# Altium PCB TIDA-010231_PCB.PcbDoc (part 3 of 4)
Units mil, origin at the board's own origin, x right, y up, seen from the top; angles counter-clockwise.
Board outline 3937.01 x 3740.16 mil, 4 copper layers (Top Layer, Signal Layer 1, Signal Layer 2, Bottom Layer), stack 65.355 mil thick; 295 components, 163 nets, 818 pads, 213 vias.
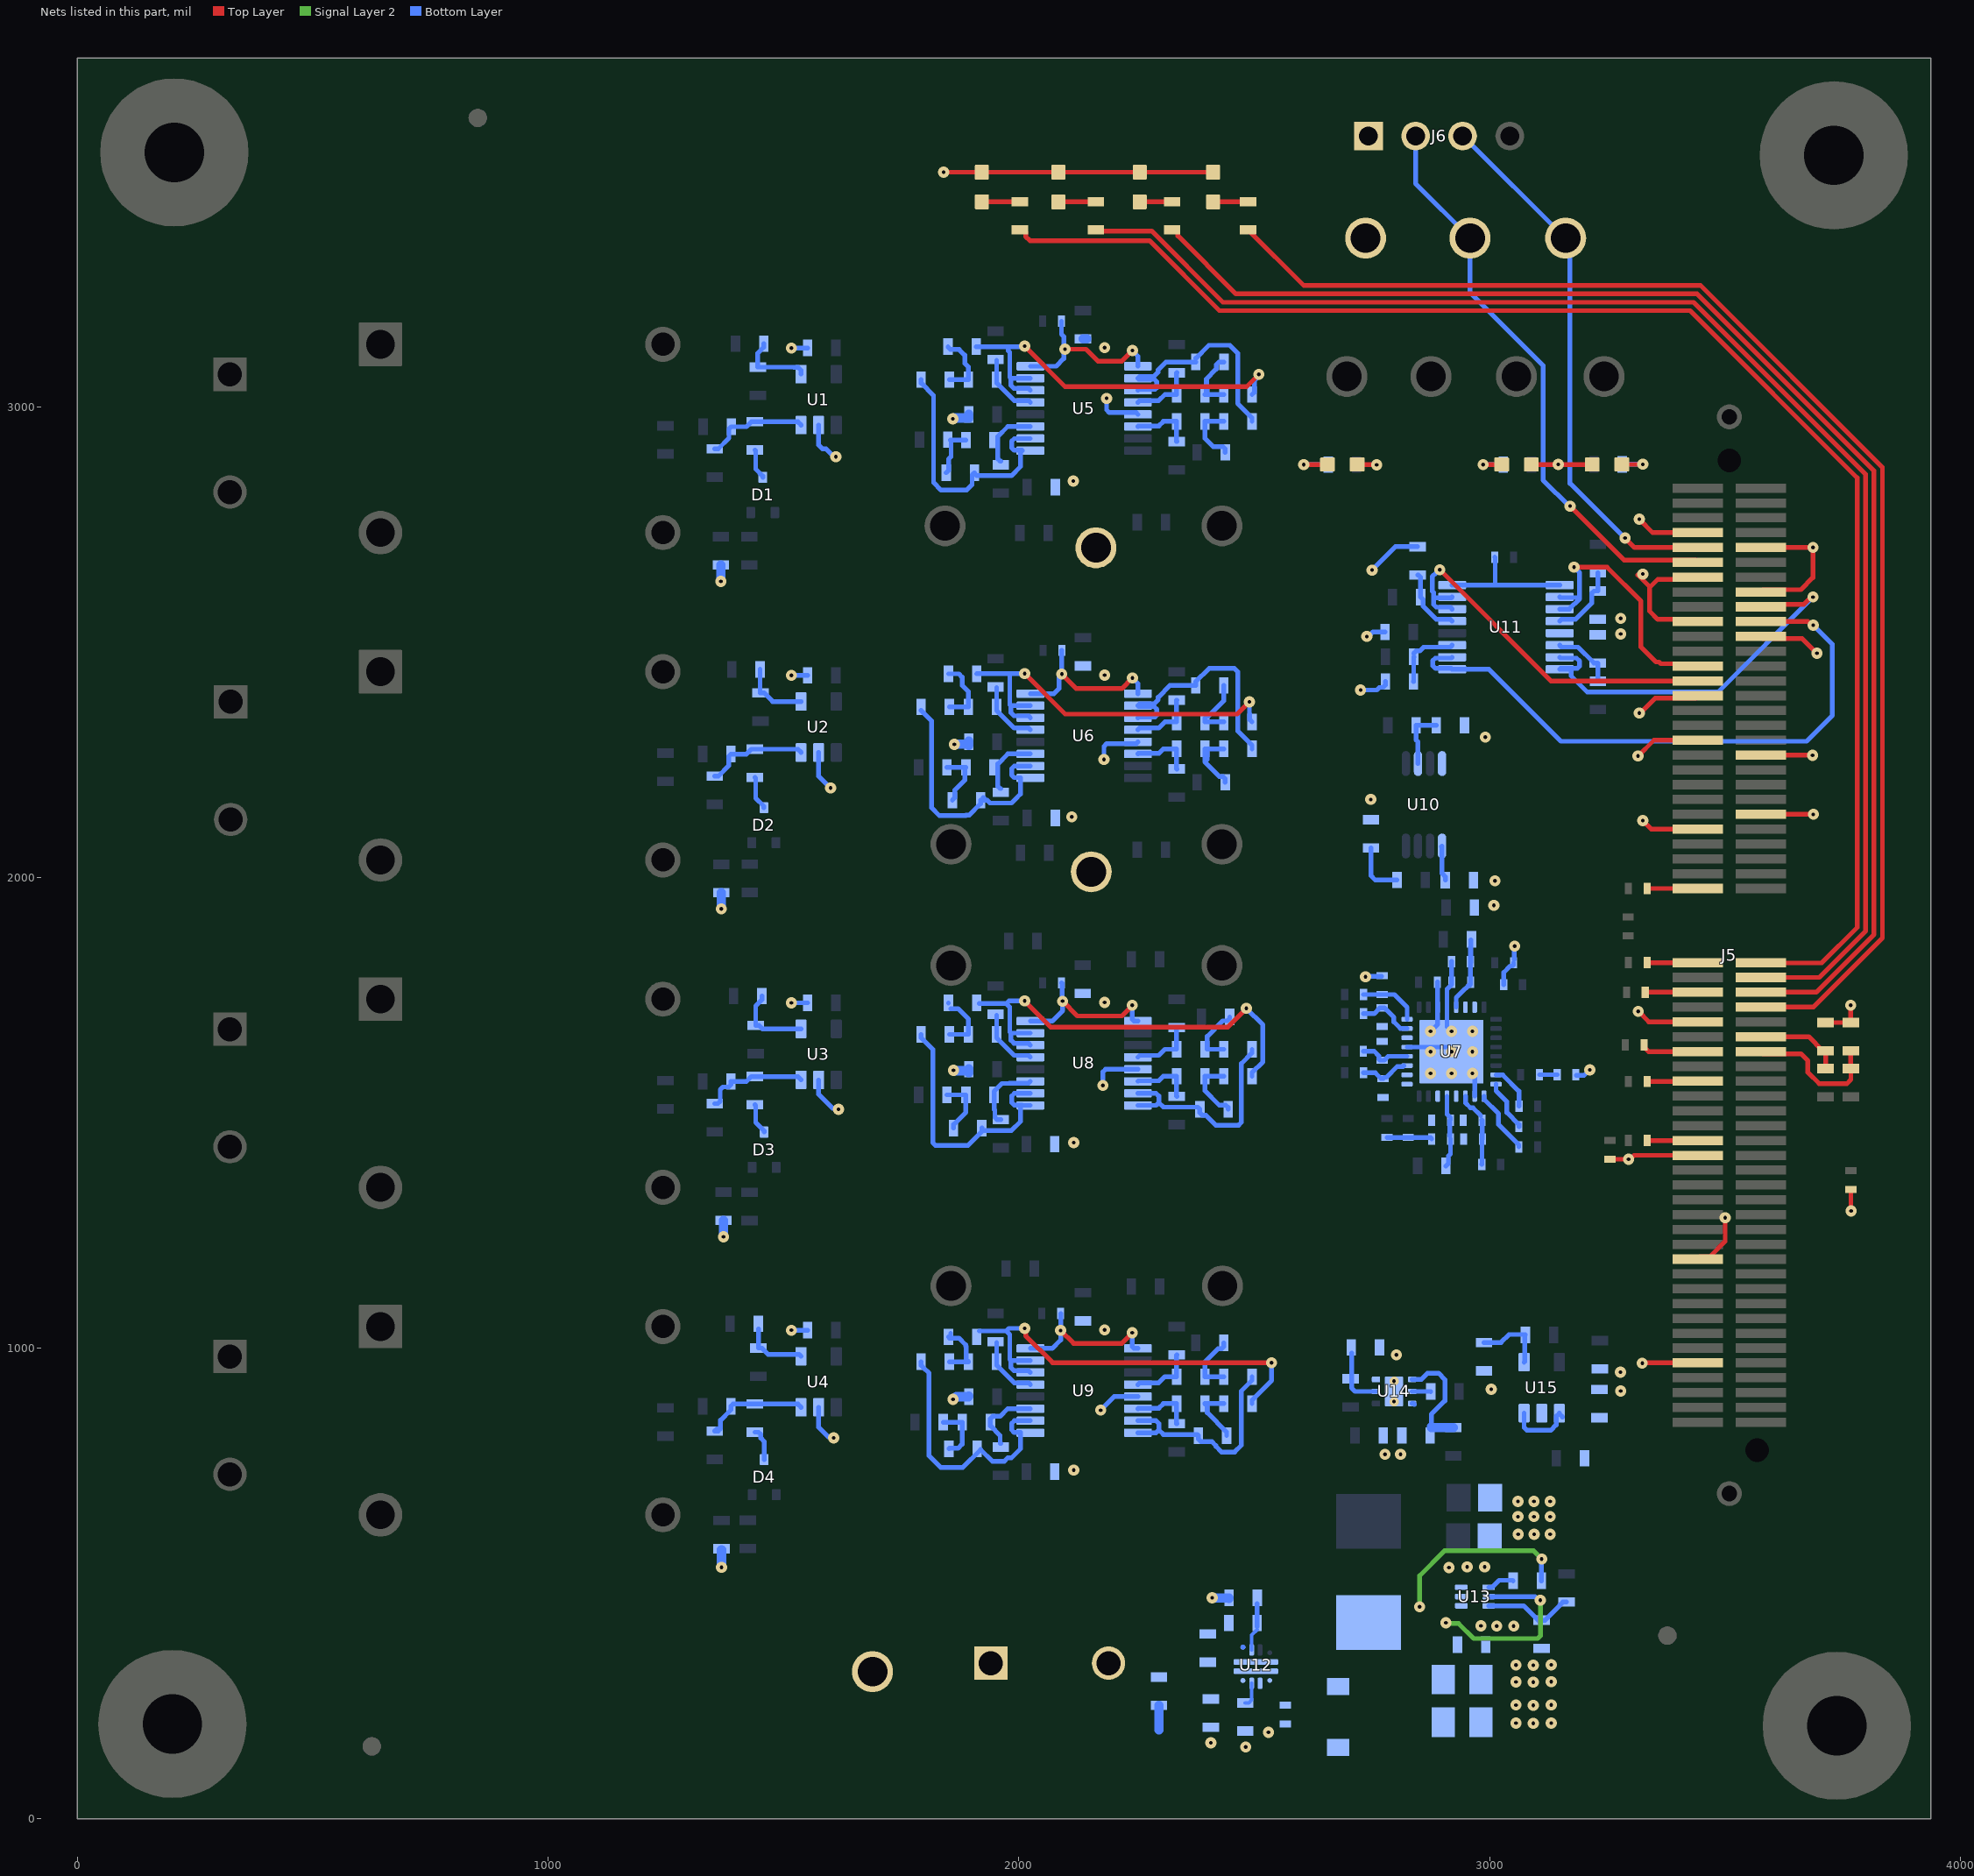
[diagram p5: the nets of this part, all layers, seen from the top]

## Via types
v1: diameter 23.62, hole 7.87, Top Layer to Bottom Layer, 211 vias
v2: diameter 19.68, hole 7.87, Top Layer to Bottom Layer, 2 vias

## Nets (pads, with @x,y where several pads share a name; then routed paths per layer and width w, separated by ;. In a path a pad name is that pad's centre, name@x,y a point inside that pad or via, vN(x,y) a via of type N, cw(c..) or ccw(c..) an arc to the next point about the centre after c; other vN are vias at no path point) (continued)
GND: C2.2 C4.2 C6.2 C8.2 C9.2 C10.2 C19.2 C20.2 C21.2 C22.2 C23.2 C24.2 C31.2 C32.2 C35.1 C36.2 C37.2 C38.2 C39.2 C46.2 C49.2 C50.2 C51.2 C52.2 C53.1 C60.2 C63.2 C64.2 C65.2 C66.2 C67.2 C68.2 C69.2 C70.2 C71.2 C72.2 C74.2 C75.2 C76.2 C77.2 C79.2 C80.1 C81.2 C83.2 C84.2 C85.2 C86.2 C87.2 C88.2 C89.2 C90.2 D5.1 D6.1 D7.1 D8.1 D9.2 D10.1 D11.1 D12.1 J5.7 J5.10 J5.13 J5.16 J5.19 J5.22 J5.29 J5.35 J5.38 J5.46 J5.47 J5.65 J5.83 J5.97 J5.111 J6.1 J7.1 R42.2 R51.1 R52.1 R81.1 R82.1 R90.1 R91.1 R99.1 R102.1 R103.1 R112.1 R113.1 R114.1 R115.1 R119.1 TP12.1 TP13.1 TP14.1 TP15.1 U1.2 U2.2 U3.2 U4.2 U5.13 U6.13 U7.1 U7.2 U7.5 U7.6 U7.11 U7.12 U7.14 U7.15 U7.26 U7.28 U7.30 U7.33 U8.13 U9.13 U10.4 U11.13 U12.8 U13.3 U14.3 U14.7@2797.02,908.01 U15.2 | length 5129.4
  Top Layer w10: v1@1837.47,3495.42 v1(1840.09,3498.03) D5.1@1921.29,3498.03 D6.1@2083.96,3498.03 D7.1@2256.73,3498.03 D8.1@2412.57,3498.03 ; D10.1@2718.55,2877.17 2718.97,2876.75 2759.52,2876.75 v1(2759.94,2876.33) ; v1@2799.83,983.8 v1(2801.83,985.8) ; D12.1@3088.56,2877.17 v1(3145.99,2877.17) D11.1@3217.94,2877.17 ; R42.2@3256.02,1401.22 v1(3295.1,1401.22) 3298.78,1401.22 3307.1,1409.54 J5.83@3442.42,1409.54 ; v1@3315.1,2257.32 3349.2,2291.42 J5.35@3442.42,2291.42 ; v1@3315.1,2642.51 3339.87,2617.74 3339.87,2615.5 ; v1(3315.91,1715.55) 3315.91,1715.44 3338.35,1693 J5.65@3442.42,1693 ; v1(3317.96,2760.83) 3346.42,2732.37 J5.7@3442.42,2732.37 ; v1@3318.6,2347.54 3352.12,2381.07 3437.58,2381.07 J5.29@3442.42,2385.91 ; v1@3324.41,967.91 3325.1,968.59 J5.111@3442.42,968.59 ; v1(3325.64,2120.57) 3343.76,2102.45 J5.47@3442.42,2102.45 ; J5.97@3442.42,1189.06 3447.27,1193.9 3467.44,1193.9 3500.37,1226.84 v1(3500.37,1277.04) ; J5.19@3442.42,2543.39 3437.58,2548.24 3357.41,2548.24 3339.87,2565.78 3339.87,2615.5 ; J5.13@3442.42,2637.88 3437.58,2633.04 3357.41,2633.04 3339.87,2615.5 ; J5.46@3576.28,2133.94 v1(3687.75,2133.94) ; J5.38@3576.28,2259.93 v1@3686.97,2259.93 ; J5.22@3576.28,2511.9 3581.13,2507.06 3664.27,2507.06 v1(3695.24,2476.08) v1@3695.24,2475.99 ; J5.16@3576.28,2606.39 3581.13,2611.23 3661.3,2611.23 3686.97,2636.9 v1(3686.97,2700.87) J5.10@3576.28,2700.87 ; R103.1@3715.31,1691.5 3715.44,1691.63 3766.95,1691.63 3767.07,1691.75 3767.07,1728.22 v1(3767.21,1728.36) ; R99.1@3767.21,1337.13 3767.63,1336.7 3767.63,1291.65 v1(3768.05,1291.23)
  Bottom Layer w10: v1(1516.53,1038.05) C90.2@1550.98,1038.05 ; v1(1516.53,1733.58) C89.2@1550.98,1733.62 ; v1(1516.53,2429.11) C88.2@1550.98,2429.13 ; v1(1516.53,3124.64) C87.2@1550.98,3124.64 ; U4.2@1574.6,874.29 1574.69,874.2 1574.69,831.76 1594.51,811.94 1603.94,811.94 v1(1606.55,809.33) ; U3.2@1574.6,1569.8 1574.6,1539.06 1603.84,1509.81 1613.92,1509.81 v1(1616.52,1507.2) ; U2.2@1574.6,2265.31 1574.69,2265.2 1574.69,2214.95 v1(1599.83,2189.81) ; U1.2@1574.6,2960.83 1574.69,2960.74 1574.69,2918.35 1582.79,2910.25 1590.55,2910.25 1607.3,2893.5 v1(1610.98,2893.5) ; v1(2173.66,868.11) 2202.48,896.93 U9.13@2252.8,896.93 ; v1(2178.35,1558.11) 2178.35,1586.58 2184.2,1592.44 U8.13@2252.8,1592.44 ; v1(2180.64,2250.68) 2180.64,2278.24 2186.5,2284.09 2248.94,2284.09 U6.13@2252.8,2287.95 ; v1(2186.18,3017.64) 2186.18,2993.18 2192.04,2987.32 2248.94,2987.32 U5.13@2252.8,2983.46 ; v1(2725.85,2397.99) 2760.33,2397.99 2765.96,2403.61 2773.46,2403.61 2778.46,2408.61 R90.1@2778.46,2416.11 ; v1(2736.33,1788.99) 2737.47,1790.13 C36.2@2770.51,1790.13 ; v1(2739.19,2511.77) 2742.87,2511.77 2752.56,2521.46 C71.2@2777.97,2521.46 ; v1(2750.34,2652.82) 2800.02,2702.51 R82.1@2847.01,2702.51 ; C60.2@2782.14,1447.52 C46.2@2827.02,1447.52 2874.39,1447.52 2876.89,1445.02 C22.2@2876.89,1444.39 ; U7.5@2824.69,1639.56 2909.33,1639.56 v1(2919.18,1629.72) ; v1(2874.62,1672.91) 2889.65,1687.94 U7.11@2889.65,1724.2 2889.57,1724.28 2889.57,1777.51 C53.1@2889.33,1777.75 ; v1(2919.18,1672.91) 2909.33,1682.75 U7.12@2909.33,1724.2 2909.33,1762.51 2919.5,1772.68 2919.37,1772.8 2919.37,1821.09 C32.2@2919.25,1821.22 ; v1(2963.66,1583.6) 2968.39,1578.87 U7.26@2968.39,1535.23 ; R52.1@3030,1772.19 3030,1797.9 3043.82,1811.72 3048.32,1811.72 3050.82,1814.22 R51.1@3050.82,1818.72 ; R51.1@3052.13,1825.72 3052.13,1852.61 v1(3053.44,1853.92) ; C35.1@3184.74,1579.5 3200.79,1579.5 3212.21,1590.93 v1(3212.94,1590.93)
  Bottom Layer w20: v1@1366.79,2629.07 C2.2@1366.79,2663.69 ; C4.2@1367.61,1967.76 1367.75,1967.76 1367.75,1933.12 v1(1367.89,1932.98) ; v1(1368.29,534.1) C8.2@1368.29,571.56 ; C6.2@1372.28,1271.38 1372.41,1271.38 1372.41,1236.72 v1(1372.55,1236.58) ; v1(1859.76,2974.06) 1860.74,2974.06 1862.73,2976.04 1893.66,2976.04 C67.2@1893.66,2983.54 ; v1(1860.24,891.11) 1861.22,891.11 1867.11,897.01 1892.69,897.01 C70.2@1893.66,897.98 ; v1(1861.2,1590.09) 1861.89,1589.4 1889.28,1589.4 1893.66,1585.02 C69.2@1893.66,1592.52 C69.2@1893.66,1593.49 ; v1(1862.75,2282.6) 1863.45,2283.29 C68.2@1893.66,2283.29 ; C68.2@1893.66,2280.53 C68.2@1893.66,2283.29 ; C68.2@1893.66,2288.52 C68.2@1893.66,2288.03 ; C68.2@1893.66,2289 C68.2@1893.66,2288.03 ; C10.2@2136.3,3143.91 C10.2@2143.8,3143.91 ; v1(2173.66,868.11) v1@2174.44,868.11 ; 2297.65,189.04 C72.2@2297.65,241.3 ; v1(2410.44,469.56) 2410.79,469.21 2446.39,469.21 R112.1@2446.39,468.86 ; C68.2@1893.66,2283.29 C68.2@1893.66,2288.03
  other v1: 2481.8,152.79 2407.9,161.48 2530.2,183.97 3056.13,203.27 3092.88,202.82 3131.03,203.54 3092.88,241.3 3056.13,241.75 3131.03,242.02 3092.88,290.48 3056.13,290.93 3131.03,291.2 3092.88,326.36 3056.13,326.81 3131.03,327.08 3015.22,409.49 3051.14,409.49 2981.76,409.96 2913.82,533.84 2952.11,535.4 2989.57,535.4 3060.72,604.52 3094.58,604.52 3128.44,604.52 3060.09,641.95 3094.26,641.95 3128.44,641.95 3060.35,674.26 3094.39,674.26 3128.44,674.26 2116.55,741.04 2777.9,774.45 2810.8,774.45 3278.59,908.86 3003.44,912.78 3277.91,948.82 3324.33,967.91 2182.26,1038.76 2116.56,1436.55 2874.62,1583.6 2919.18,1583.6 2874.62,1629.72 2963.66,1629.72 2963.66,1672.91 2182.26,1734.28 3009.16,1940.45 3011.57,1992.9 2112.29,2128.69 2747.48,2165.54 3315.13,2258.06 3686.09,2259.47 2990.96,2297.82 3317.96,2349.03 2182.26,2429.79 3278.59,2517.32 3278.59,2550.06 1366.93,2628.93 3325.64,2644.47 2115.4,2841.81 2182.26,3125.3
  other v2: 2797.02,886.36 2797.02,929.67
GPIO4: J5.68 R101.2 R103.2 | length 189.7
  Top Layer w10: J5.68@3576.28,1661.5 3677.81,1661.5 3707.81,1631.5 3715.31,1631.5 3713.78,1629.98 R101.2@3713.78,1593.91
GPIO5: J5.70 R100.1 R102.2 | length 299
  Top Layer w10: J5.70@3576.28,1630.01 3581.13,1625.17 3661.3,1625.17 3676.12,1610.34 3676.12,1585.86 3700.18,1561.8 3758.81,1561.8 3767.67,1570.66 R100.1@3767.67,1593.91 3767.07,1594.51 R102.2@3767.07,1631.75
IntADC1In: J5.25 U11.10 U11.11 | length 574.1
  Top Layer w10: v1(3179.25,2659.1) 3249.43,2659.1 3321.61,2586.93 3321.61,2489.55 3353.47,2457.69 3359.87,2457.69 3363.8,2453.75 3437.58,2453.75 J5.25@3442.42,2448.91
  Bottom Layer w10: U11.11@3148.79,2569.97 3169.46,2569.97 3191.19,2591.7 3191.19,2593.99 ; U11.10@3148.79,2595.56 3150.04,2594.3 3190.87,2594.3 3191.19,2593.99 ; v1(3179.25,2659.1) 3191.19,2647.16 3191.19,2593.99
IntADC2In: J5.27 U11.6 U11.7 | length 813.7
  Top Layer w10: v1(2894.14,2653.48) 3130.21,2417.41 J5.27@3442.42,2417.41
  Bottom Layer w10: v1(2894.14,2653.48) 2888.23,2647.56 2886.9,2647.56 2878.04,2638.7 2878.04,2608.1 2881.05,2605.09 2881.05,2589.84 ; U11.6@2920.44,2569.97 2916.58,2573.83 2886.9,2573.83 2881.05,2579.68 2881.05,2589.84 ; U11.7@2920.44,2595.56 2918.71,2593.83 2885.03,2593.83 2881.05,2589.84
IntADC3In: J5.20 U11.1 U11.2 | length 1316.5
  Top Layer w10: J5.20@3576.28,2543.39 3676.34,2543.39 3683.87,2535.87 v1(3687.56,2535.87)
  Bottom Layer w10: U11.2@2920.44,2467.61 2918.71,2465.87 2884.86,2465.87 2879,2460.02 2879,2450 2885.25,2443.75 2918.71,2443.75 U11.1@2920.44,2442.02 2998.53,2442.02 3151.46,2289.08 3673.39,2289.08 3728.35,2344.03 3728.35,2495.08 v1(3687.56,2535.87)
IntADC4In: J5.18 U11.15 U11.16 | length 868.5
  Top Layer w10: J5.18@3576.28,2574.89 3581.13,2579.73 3667.46,2579.73 3683.28,2595.56 v1(3686.97,2595.56)
  Bottom Layer w10: U11.15@3148.79,2467.61 3150.52,2465.87 3184.52,2465.87 3191.19,2459.2 3191.19,2448.8 3186.13,2443.75 3150.52,2443.75 U11.16@3148.79,2442.02 3169.46,2442.02 3173.32,2438.16 3173.32,2427.88 3207.39,2393.81 3485.22,2393.81 v1(3686.97,2595.56)
NetC1_1: C1.1 R3.2 R4.2 U1.3 | length 221.7
  Bottom Layer w10: C1.1@1353.67,2910.42 1361.17,2910.42 1384.08,2933.33 1384.08,2952.48 R4.2@1389.08,2957.48 1421.11,2957.48 1431.58,2967.95 1530.39,2967.95 1537.2,2961.14 U1.3@1537.2,2960.83
NetC3_1: C3.1 R8.2 R9.2 U2.3 | length 222.2
  Bottom Layer w10: C3.1@1353.67,2214.91 1361.17,2214.91 1383.23,2236.97 1383.23,2256.94 R9.2@1388.23,2261.94 1421.11,2261.94 1431.58,2272.42 1530.39,2272.42 1537.2,2265.6 U2.3@1537.2,2265.31
NetC5_1: C5.1 R13.2 R14.2 U3.3 | length 228.7
  Bottom Layer w10: C5.1@1353.67,1519.4 1360.32,1519.36 1365.36,1524.4 1365.36,1548.85 1371.22,1554.71 1383.23,1554.71 1388.23,1559.71 R14.2@1388.23,1566.41 1421.11,1566.41 1431.58,1576.88 R13.2@1439.08,1576.92 1530.39,1576.88 1537.2,1570.07 U3.3@1537.2,1569.8
NetC7_1: C7.1 R18.2 R19.2 U4.3 | length 231.9
  Bottom Layer w10: C7.1@1358.23,828.38 1353.67,823.83 1361.11,823.83 1366.17,828.89 1366.17,846.9 1388.23,868.95 R19.2@1388.23,876.45 1393.19,881.41 1439.02,881.41 R18.2@1439.08,881.41 1530.39,881.35 1537.2,874.54 U4.3@1537.2,874.23
NetC11_2: C11.2 R24.2 U5.3 | length 133.7
  Bottom Layer w10: C11.2@1961.35,2884.2 1960.2,2884.2 1955.2,2889.2 1955.2,2929.13 1955.2,2936.63 1976.44,2957.87 U5.3@2024.45,2957.87
NetC12_2: C12.2 R26.2 U5.5 | length 137.2
  Bottom Layer w10: C12.2@1952.76,3098.56 R26.2@1952.76,3057.56 1952.76,3050.06 1989.9,3012.91 2020.59,3012.91 U5.5@2024.45,3009.06
NetC13_1: C13.1 C14.2 R28.2 | length 162.3
  Bottom Layer w10: C14.2@2398.7,3029.46 2398.7,3059 ; C13.1@2435.39,3025.77 C14.2@2395,3025.77 2397.76,3028.53 2397.76,3058.27 2419.32,3079.83 2419.32,3089.08 2425.18,3094.94 2435.57,3094.94 R28.2@2435.82,3095.19
NetC13_2: C13.2 C18.2 U5.6 U5.7 | length 867.6
  Top Layer w10: v1(2012.13,3128.56) 2098.35,3042.33 2483.65,3042.33 v1(2509.72,3068.4)
  Bottom Layer w10: C18.2@1909.45,3127.55 1977.66,3127.55 ; v1(2012.13,3128.56) 2011.12,3127.55 1977.66,3127.55 ; U5.6@2024.45,3034.65 2020.59,3038.5 1989.59,3038.5 1983.07,3045.02 1983.07,3060.24 ; U5.7@2024.45,3060.24 1983.07,3060.24 ; C13.2@2495.39,3025.77 2500.39,3030.77 2500.39,3055.38 2509.72,3064.71 v1(2509.72,3068.4) ; 1977.66,3127.55 1977.66,3118.47 1980.66,3115.47 1980.66,3062.65 1983.07,3060.24
NetC14_1: C14.1 R21.1 U5.12 | length 135.6
  Bottom Layer w10: U5.12@2252.8,3009.06 2256.65,3012.91 2297.14,3012.91 2310,3025.77 C14.1@2335,3025.77 2335,3071.6 R21.1@2335.47,3072.07
NetC15_1: C15.1 C16.2 R29.2 | length 136.3
  Bottom Layer w10: C15.1@2435.39,2968.68 C16.2@2395,2968.68 2395,2932.97 2412.64,2915.33 2433.31,2915.33 2438.31,2910.33 R29.2@2438.31,2902.83
NetC15_2: C15.2 R28.1 U5.10 U5.11 | length 503.8
  Bottom Layer w10: U5.11@2252.8,3034.65 2254.53,3036.38 2289.02,3036.38 2293.15,3040.5 2293.15,3052.65 2287.29,3058.5 2254.53,3058.5 U5.10@2252.8,3060.24 2256.65,3064.09 2286.51,3064.09 2295.81,3073.39 2295.81,3078.11 2312.64,3094.94 2375.57,3094.94 R28.1@2375.82,3095.19 ; R28.1@2375.82,3102.69 2403.59,3130.46 2448,3130.46 2464.97,3113.49 2464.97,3006.61 2495.39,2976.18 C15.2@2495.39,2968.68
NetC16_1: C16.1 R22.1 U5.14 | length 129.7
  Bottom Layer w10: U5.14@2252.8,2957.87 2253.79,2958.87 2297.32,2958.87 2307.14,2968.68 C16.1@2335,2968.68 2335,2926.34 R22.1@2335.47,2925.87
NetC17_1: C17.1 R23.2 R24.1 | length 106.8
  Bottom Layer w10: C17.1@1845.51,2859.65 1850.51,2864.65 1850.51,2888.37 1855.95,2893.82 1855.95,2927.98 1854.8,2929.13 R24.1@1887.32,2929.13
NetC17_2: C17.2 R25.1 U5.1 U5.2 | length 577.4
  Bottom Layer w10: R25.1@1792.36,3057.56 1792.36,3050.06 1818.77,3023.65 1818.77,2859.65 1818.55,2859.43 1818.55,2838.88 1834.85,2822.58 1888.68,2822.58 1900.51,2834.4 1900.51,2854.65 C17.2@1905.51,2859.65 1905.51,2858.45 1910.51,2853.45 1984.18,2853.45 2003.43,2872.7 2003.43,2902.83 2007.29,2906.69 2005.73,2906.69 2006.15,2907.11 2005.88,2907.38 1990.15,2907.38 1984.48,2913.05 1984.48,2926.43 1990.34,2932.28 U5.2@2024.45,2932.28
NetC18_1: C18.1 R25.2 R26.1 | length 139.1
  Bottom Layer w10: C18.1@1849.45,3127.55 1849.45,3126.39 1854.45,3121.39 1872.89,3121.39 1885.05,3109.22 1885.05,3091.94 1892.76,3084.24 R26.1@1892.76,3057.56 R25.2@1852.36,3057.56
NetC21_1: C21.1 C22.1 L1.1 U7.29 | length 149.6
  Bottom Layer w10: L1.1@2907.23,1387.03 2912.23,1392.03 2912.23,1407.9 2916.89,1412.56 C22.1@2916.89,1444.39 ; U7.29@2909.33,1535.23 2909.33,1496.97 2916.89,1489.42 2916.89,1484.92 2915.76,1483.79 C22.1@2915.76,1450.63
NetC23_1: C23.1 C24.1 R31.1 U7.27 | length 152.4
  Bottom Layer w10: U7.27@2948.7,1535.23 2948.78,1535.15 2948.78,1521.05 2959.29,1510.54 2964.57,1510.54 C24.1@2981.01,1494.1 ; R31.1@2983.44,1390.22 2983.95,1390.73 2983.95,1443.88 C23.1@2984.45,1444.39 2984.06,1444.78 2984.06,1483.86 C24.1@2983.66,1484.25
NetC25_2: C25.2 R35.2 U6.3 | length 133.7
  Bottom Layer w10: C25.2@1961.35,2188.69 1960.2,2188.69 1955.2,2193.69 1955.2,2233.62 1955.2,2241.12 1976.44,2262.36 U6.3@2024.45,2262.36
NetC26_2: C26.2 R37.2 U6.5 | length 137.2
  Bottom Layer w10: C26.2@1952.76,2403.04 R37.2@1952.76,2362.05 1952.76,2354.55 1989.9,2317.4 2020.59,2317.4 U6.5@2024.45,2313.54
NetC27_1: C27.1 C28.2 R40.2 | length 136.4
  Bottom Layer w10: C27.1@2435.39,2330.26 C28.2@2395,2330.26 2395,2337.76 2400,2342.76 2402.86,2342.76 2435.45,2375.35 R40.2@2435.45,2407.85
NetC27_2: C27.2 C34.2 U6.6 U6.7 | length 842.7
  Top Layer w10: v1(2012.13,2433.04) 2098.35,2346.82 2463.58,2346.82 v1(2489.65,2372.89)
  Bottom Layer w10: C34.2@1910.35,2432.39 1911.01,2433.04 1980.6,2433.04 ; v1(2012.13,2433.04) 1980.6,2433.04 ; U6.6@2024.45,2339.13 2020.59,2342.99 1989.59,2342.99 1983.07,2349.51 1983.07,2364.72 ; U6.7@2024.45,2364.72 1983.07,2364.72 ; v1(2489.65,2372.89) 2489.65,2348.61 2490.39,2347.87 2490.39,2335.26 C27.2@2495.39,2330.26 ; 1980.6,2433.04 1980.6,2420.01 1980.65,2419.95 1980.65,2367.14 1983.07,2364.72
NetC28_1: C28.1 R32.1 U6.12 | length 135.6
  Bottom Layer w10: U6.12@2252.8,2313.54 2256.65,2317.4 2297.14,2317.4 2310,2330.26 C28.1@2335,2330.26 2335,2376.08 R32.1@2335.47,2376.56
NetC29_1: C29.1 C30.2 R41.2 | length 151.4
  Bottom Layer w10: 2400,2250.68 C30.2@2400,2268.17 ; C29.1@2435.39,2273.17 C30.2@2395,2273.17 2395,2245.3 2425.81,2214.49 2433.31,2214.49 2438.31,2209.49 R41.2@2438.31,2201.99
NetC29_2: C29.2 R40.1 U6.10 U6.11 | length 529.9
  Bottom Layer w10: U6.11@2252.8,2339.13 2254.53,2340.87 2289.02,2340.87 2293.15,2344.99 2293.15,2357.13 2287.29,2362.99 2254.53,2362.99 U6.10@2252.8,2364.72 2256.65,2368.58 2286.51,2368.58 2295.81,2377.87 2295.81,2382.6 2321.06,2407.85 R40.1@2375.45,2407.85 2375.45,2415.35 2404.05,2443.95 2457.98,2443.95 2464.97,2436.96 2464.97,2387 2464.97,2311.1 2495.39,2280.67 C29.2@2495.39,2273.17
NetC30_1: C30.1 R33.1 U6.14 | length 129.7
  Bottom Layer w10: U6.14@2252.8,2262.36 2253.79,2263.36 2297.32,2263.36 2307.14,2273.17 C30.1@2335,2273.17 2335,2230.83 R33.1@2335.47,2230.35
NetC31_1: C31.1 C32.1 L2.1 U7.13 | length 188.1
  Bottom Layer w10: U7.13@2929.02,1724.2 2929.02,1744.5 2941.82,1757.3 2954.69,1770.18 2957,1770.18 2959.5,1772.68 C31.1@2959.5,1777.18 2959.37,1777.3 2959.37,1818.85 2960.41,1819.88 L2.1@2960.41,1867.35 ; C32.1@2959.25,1821.22 L2.1@2959.25,1851.72
NetC33_1: C33.1 R34.2 R35.1 | length 121.8
  Bottom Layer w10: R34.2@1846.93,2233.62 R35.1@1887.32,2233.62 1885.4,2231.7 1885.4,2206.98 1863.68,2185.26 1863.68,2169.08 C33.1@1858.68,2164.08
NetC33_2: C33.2 R36.1 U6.1 U6.2 | length 557.5
  Bottom Layer w10: R36.1@1792.36,2354.55 1814.57,2332.34 1814.57,2147.57 1830.74,2131.39 1887.06,2131.39 1887.81,2132.14 1894.24,2132.14 1918.68,2156.58 C33.2@1918.68,2164.08 1932.38,2164.08 1938.52,2157.94 1984.18,2157.94 1991.73,2165.48 2003.43,2177.19 2003.43,2211.87 1990.15,2211.87 1984.48,2217.54 1984.48,2230.91 1990.34,2236.77 U6.2@2024.45,2236.77 ; C33.2@1924.38,2169.77 C33.2@1928.34,2165.81
NetC34_1: C34.1 R36.2 R37.1 | length 141.2
  Bottom Layer w10: C34.1@1850.35,2432.39 1872.42,2432.39 1879.45,2425.36 1879.45,2407.86 1892.76,2394.55 R37.1@1892.76,2362.05 R36.2@1852.36,2362.05
NetC35_2: C35.2 R43.2 | length 37.6
  Bottom Layer w10: R43.2@3105.9,1580.76 C35.2@3143.48,1580.76
NetC36_1: C36.1 R39.2 U7.8 | length 129.4
  Bottom Layer w10: R39.2@2732.13,1751.19 2732.17,1751.23 2771.61,1751.23 C36.1@2771.65,1751.27 2797.62,1751.27 2824.69,1724.2 U7.8@2824.69,1698.61
NetC37_1: C37.1 R45.2 U7.7 | length 121.4
  Bottom Layer w10: R45.2@2732.13,1710.63 2754.94,1710.63 2767.15,1722.84 C37.1@2771.65,1722.84 2776.15,1722.84 2796.53,1702.47 2796.53,1692.99 2810.51,1679.01 2824.61,1679.01 U7.7@2824.69,1678.93
NetC40_2: C40.2 R54.2 U8.3 | length 156.4
  Bottom Layer w10: C40.2@1961.35,1485.3 1953.85,1485.3 1948.85,1490.3 1948.85,1505.68 1947.32,1507.2 R54.2@1947.32,1538.11 1947.32,1545.61 1963.86,1562.15 1979.07,1562.15 1979.92,1562.99 2020.59,1562.99 U8.3@2024.45,1566.85
NetC41_2: C41.2 R56.2 U8.5 | length 137.2
  Bottom Layer w10: C41.2@1952.76,1707.53 R56.2@1952.76,1666.53 1952.76,1659.04 1989.9,1621.89 2020.59,1621.89 U8.5@2024.45,1618.03
NetC42_1: C42.1 C43.2 R58.2 | length 138.9
  Bottom Layer w10: C42.1@2435.39,1577.66 C43.2@2395,1577.66 2395,1547.02 2425.81,1516.22 2439.35,1516.22 2444.35,1511.22 R58.2@2444.35,1507.51
NetC42_2: C42.2 C48.2 U8.6 U8.7 | length 947.2
  Top Layer w10: v1(2012.13,1737.53) 2067.91,1681.75 2443.29,1681.75 v1(2483.3,1721.76)
  Bottom Layer w10: C48.2@1915.35,1731.92 1927.39,1731.92 1927.45,1731.98 1973.11,1731.98 ; v1(2012.13,1737.53) 1978.66,1737.53 1973.11,1731.98 ; U8.6@2024.45,1643.62 2020.59,1647.48 1989.59,1647.48 1983.07,1654 1983.07,1669.21 ; U8.7@2024.45,1669.21 1983.07,1669.21 ; v1(2483.3,1721.76) 2518.27,1686.8 2518.27,1608.03 2495.39,1585.16 C42.2@2495.39,1577.66 ; 1973.11,1731.98 1980.65,1724.44 1980.65,1671.63 1983.07,1669.21
NetC43_1: C43.1 R49.1 U8.14 | length 129.7
  Bottom Layer w10: U8.14@2252.8,1566.85 2253.79,1567.84 2297.32,1567.84 2307.14,1577.66 C43.1@2335,1577.66 2335,1535.31 R49.1@2335.47,1534.84
NetC44_1: C44.1 C45.2 R59.2 | length 129.5
  Bottom Layer w10: C44.1@2435.39,1634.74 2400,1634.74 2400,1662.13 2433.16,1695.3 2442.73,1695.3 2447.73,1700.3 R59.2@2447.73,1703.45
NetC44_2: C44.2 R58.1 U8.15 U8.16 | length 474.3
  Bottom Layer w10: U8.16@2252.8,1515.67 2291.46,1515.67 2297.32,1521.53 ; U8.15@2252.8,1541.26 2291.46,1541.26 2297.32,1535.4 2297.32,1521.53 ; C44.2@2495.39,1634.74 2495.39,1627.24 2472.52,1604.37 2472.52,1479.52 2466.66,1473.66 2418.2,1473.66 2396.85,1495.01 2389.35,1495.01 2384.35,1500.01 R58.1@2384.35,1507.51 2379.89,1511.97 2306.88,1511.97 2297.32,1521.53
NetC45_1: C45.1 R50.1 U8.12 | length 135.6
  Bottom Layer w10: U8.12@2252.8,1618.03 2256.65,1621.89 2297.14,1621.89 2310,1634.74 C45.1@2335,1634.74 2335,1680.57 R50.1@2335.47,1681.04
NetC47_1: C47.1 R53.2 R54.1 | length 121.8
  Bottom Layer w10: R53.2@1846.93,1538.11 R54.1@1887.32,1538.11 1887.32,1501.18 1861.16,1475.02 C47.1@1861.16,1467.52
NetC47_2: C47.2 R55.1 U8.1 U8.2 | length 600
  Bottom Layer w10: R55.1@1792.36,1666.54 1792.36,1659.03 1816.93,1634.47 1816.93,1436.55 1822.79,1430.7 1891.84,1430.7 C47.2@1921.16,1460.02 ; U8.1@2024.45,1515.67 U8.1@2007.29,1515.67 ; U8.2@2024.45,1541.26 1990.34,1541.26 1984.48,1535.4 1984.48,1522.03 1990.15,1516.36 2005.88,1516.36 2006.15,1516.09 2005.73,1515.67 U8.1@2007.29,1515.67 ; C47.2@1921.16,1460.02 1923.57,1462.43 1984.18,1462.43 2003.43,1481.67 2003.43,1511.81 U8.1@2007.29,1515.67 ; C47.2@1921.16,1460.02 C47.2@1921.16,1467.52 C47.2@1921.16,1460.02
NetC48_1: C48.1 R55.2 R56.1 | length 120.3
  Bottom Layer w10: C48.1@1850.35,1732.72 C48.1@1850.35,1733.58 ; R55.2@1852.36,1666.54 R56.1@1892.76,1666.53 1892.76,1699.03 1870.71,1721.08 C48.1@1855.35,1721.08
NetC49_1: C49.1 R60.2 U7.4 | length 107.9
  Bottom Layer w10: R60.2@2732.08,1630.68 2754.58,1630.68 2764.65,1620.61 2764.65,1614 2767.15,1611.5 C49.1@2771.65,1611.5 2776.15,1611.5 2784.52,1619.87 U7.4@2824.69,1619.87
NetC52_1: C52.1 R62.2 U7.3 | length 100.8
  Bottom Layer w10: R62.2@2732.1,1585.02 2757.15,1585.02 2769.34,1572.83 C52.1@2772.51,1572.83 ; C52.1@2773.84,1572.83 2776.34,1575.33 2780.84,1575.33 2803.8,1598.3 2816.07,1598.3 U7.3@2817.88,1600.11
NetC54_2: C54.2 R66.2 U9.3 | length 156
  Bottom Layer w10: C54.2@1961.35,797.66 1960.2,797.66 1960.2,814.35 1939.45,835.1 R66.2@1939.45,842.6 1939.45,850.1 1944.45,855.1 1960.2,855.1 1976.44,871.34 U9.3@2024.45,871.34
NetC55_2: C55.2 R68.2 U9.5 | length 137.2
  Bottom Layer w10: C55.2@1952.76,1012.02 R68.2@1952.76,971.02 1952.76,963.52 1989.9,926.38 2020.59,926.38 U9.5@2024.45,922.52
NetC56_1: C56.1 C57.2 R70.2 | length 127.7
  Bottom Layer w10: C56.1@2435.39,882.15 C57.2@2395,882.15 2400,877.15 2400,863 2441.41,821.59 R70.2@2441.41,814.09
NetC56_2: C56.2 C62.2 U9.6 U9.7 | length 935.2
  Top Layer w10: v1(2012.13,1042.02) 2014.39,1039.75 2014.39,1026.37 2071.66,969.11 v1(2536.91,969.11)
  Bottom Layer w10: C62.2@1915.35,1036.41 1927.39,1036.41 1927.45,1036.47 1973.11,1036.47 ; v1(2012.13,1042.02) 1978.66,1042.02 1973.11,1036.47 ; U9.6@2024.45,948.11 2020.59,951.97 1989.59,951.97 1983.07,958.49 1983.07,973.7 ; U9.7@2024.45,973.7 1983.07,973.7 ; C56.2@2495.39,882.15 2495.39,889.65 2536.91,931.17 v1(2536.91,969.11) ; 1973.11,1036.47 1980.65,1028.93 1980.65,976.11 1983.07,973.7
NetC57_1: C57.1 R63.1 U9.14 | length 129.7
  Bottom Layer w10: U9.14@2252.8,871.34 2253.79,872.33 2297.32,872.33 2307.14,882.15 C57.1@2335,882.15 2335,839.8 R63.1@2335.47,839.33
NetC58_1: C58.1 C59.2 R71.2 | length 133.4
  Bottom Layer w10: C58.1@2435.39,939.23 C59.2@2395,939.23 2395,970.65 2422.96,998.6 2430.46,998.6 2435.46,1003.6 R71.2@2435.46,1011.1
NetC58_2: C58.2 R70.1 U9.15 U9.16 | length 468.7
  Bottom Layer w10: U9.16@2252.8,820.16 2291.46,820.16 2297.32,826.02 ; U9.15@2252.8,845.75 2291.46,845.75 2297.32,839.89 2297.32,826.02 ; C58.2@2495.39,939.23 2495.39,931.73 2472.52,908.86 2472.52,793.63 2458.22,779.33 2430.46,779.33 2418.54,791.25 2418.54,792.86 2409.81,801.59 2386.41,801.59 2381.41,806.59 R70.1@2381.41,814.09 2379.04,816.46 2306.88,816.46 2297.32,826.02
NetC59_1: C59.1 R64.1 U9.12 | length 135.6
  Bottom Layer w10: U9.12@2252.8,922.52 2256.65,926.38 2297.14,926.38 2310,939.23 C59.1@2335,939.23 2335,985.06 R64.1@2335.47,985.53
NetC61_1: C61.1 R65.2 R66.1 | length 119.1
  Bottom Layer w10: R65.2@1839.05,842.6 R66.1@1879.45,842.6 1879.45,795.95 1870.71,787.21 1852.34,787.21 C61.1@1851.42,786.29
NetC61_2: C61.2 R67.1 U9.1 U9.2 | length 560.2
  Bottom Layer w10: R67.1@1792.36,971.02 1792.36,963.52 1797.36,958.52 1809.05,946.83 1809.05,771.19 1834.12,746.13 1880.41,746.13 1918.7,784.43 1943.34,759.79 1969.18,759.79 1976.31,766.92 1984.18,766.92 2003.43,786.16 2003.43,820.85 1990.15,820.85 1984.48,826.51 1984.48,839.89 1990.34,845.75 U9.2@2024.45,845.75
NetC62_1: C62.1 R67.2 R68.1 | length 129.9
  Bottom Layer w10: C62.1@1850.35,1023.91 1852.89,1021.38 1872.55,1021.38 1887.1,1006.83 1887.1,1004.23 1887.81,1003.52 1887.81,975.97 R68.1@1892.76,971.02 R67.2@1852.36,971.02 ; C62.1@1855.05,1023.91 C62.1@1855.05,1031.41
NetC63_1: C63.1 R73.2 U10.2 | length 125.6
  Bottom Layer w10: U10.2@2847.75,2241.9 2847.79,2287.95 2843.71,2292.03 R73.2@2843.71,2322.92 C63.1@2886.58,2322.92
NetC65_1: C65.1 U10.5 | length 77.6
  Bottom Layer w10: U10.5@2897.46,2065.22 U10.5@2898.94,2066.7 2898.94,2008.58 2905.94,2001.57 C65.1@2905.94,1994.07
NetC66_1: C66.1 R74.1 | length 117.7
  Bottom Layer w10: C66.1@2748.04,2062.37 2748.04,2003.68 2757.26,1994.46 R74.1@2803.18,1994.46
NetC73_1: C73.1 U13.4 | length 58.7
  Bottom Layer w10: U13.4@2998.04,491.88 3005.32,491.88 3020.23,506.79 3048.97,506.79 C73.1@3050.09,505.66
NetC73_2: C73.2 L3.1 U13.2 | length 400.4
  Signal Layer 2 w10: v1(2851.34,450.68) 2851.34,516.57 2904.18,569.41 3093.41,569.41 v1(3110.73,552.09)
  Bottom Layer w10: C73.2@3110.09,505.66 3110.09,551.45 v1@3110.28,551.64
NetC74_1: C74.1 C75.1 C76.1 D9.1 U12.6 U13.1 U13.5 | length 405.7
  Signal Layer 2 w10: v1(2907.26,416.71) 2908.93,415.04 2934.07,415.04 2966.13,382.97 3102,382.97 3107.86,388.83 v1(3107.86,464.35)
  Bottom Layer w10: U13.5@2998.04,472.2 3096.33,472.2 3104.18,464.35 v1(3107.86,464.35)
NetC77_1: C77.1 R106.1 U14.4 U14.6 | length 247
  Bottom Layer w10: U14.6@2835.41,882.42 2838.36,882.42 U14.6@2840.33,880.45 ; U14.4@2835.41,933.6 2855.21,933.6 2868.35,946.74 2891.4,946.74 2905.1,933.04 2905.1,888.1 2876.18,859.18 2876.18,832.84
  Bottom Layer w20: 2876.18,832.84 2876.18,831.12 R106.1@2922.78,831.12
NetC83_1: C83.1 U12.10
NetC84_1: C84.1 U12.7
NetC85_1: C85.1 R116.2 U15.1 U15.3 | length 144.4
  Bottom Layer w10: U15.3@3073.33,861.78 3073.33,831.35 3079.37,825.31 3129.74,825.31 3141.32,836.89 3141.32,854.97 U15.1@3148.13,861.78 3148.13,860.44 U15.1@3154.94,853.63
NetD1_3: D1.3 R3.1 | length 65
  Bottom Layer w10: R3.1@1439.08,2907.95 1440.7,2906.33 1440.7,2867.58 1455.85,2852.43 D1.3@1455.85,2849.87
NetD2_3: D2.3 R8.1 | length 72.1
  Bottom Layer w10: R8.1@1439.08,2212.44 1440.7,2210.82 1440.7,2168.53 1458.35,2150.87 D2.3@1458.35,2148.31
NetD3_3: D3.3 R13.1 | length 66.2
  Bottom Layer w10: R13.1@1439.08,1516.92 1440.7,1515.31 1440.7,1479.5 1458.79,1461.4 D3.3@1458.79,1458.84
NetD4_3: D4.3 R18.1 | length 70.6
  Bottom Layer w10: R18.1@1439.08,821.41 1446.58,821.41 1451.58,816.41 1451.58,808.91 1458.79,801.7 D4.3@1458.79,763.33
NetD5_2: D5.2 R88.2 | length 81.5
  Top Layer w10: D5.2@1921.29,3435.04 2000,3435.04 R88.2@2001.97,3437.01
NetD6_2: D6.2 R89.2 | length 80.5
  Top Layer w10: D6.2@2083.96,3435.04 2161.69,3435.04 R89.2@2163.66,3437.01
NetD7_2: D7.2 R93.2 | length 69.4
  Top Layer w10: D7.2@2256.73,3435.04 2323.39,3435.04 R93.2@2325.35,3437.01
NetD8_2: D8.2 R94.2 | length 75.3
  Top Layer w10: D8.2@2412.57,3435.04 2485.08,3435.04 R94.2@2487.05,3437.01
NetD10_2: D10.2 R111.1 | length 102.6
  Top Layer w10: v1(2605.27,2876.82) 2605.45,2876.99 2655.38,2876.99 D10.2@2655.56,2877.17
  Bottom Layer w10: v1@2605.03,2876.58 v1(2605.27,2876.82) R111.1@2657.06,2876.82
NetD11_2: D11.2 R108.2 | length 88.8
  Top Layer w10: D11.2@3280.93,2877.17 3281.11,2877.35 3325.46,2877.35 v1(3325.64,2877.52)
  Bottom Layer w10: R108.2@3281.73,2877.52 v1(3325.64,2877.52)
NetD12_2: D12.2 R117.1 | length 83.2
  Top Layer w10: v1(2986.08,2876.82) 2986.25,2876.99 3025.39,2876.99 D12.2@3025.57,2877.17
  Bottom Layer w10: v1@2985.72,2877.17 v1(2986.08,2876.82) R117.1@3029.11,2876.82
NetJ5_9: J5.9 J6.3 TP10.1 | length 1164.4
  Top Layer w10: v1(3287.67,2721.05) 3307.85,2700.87 J5.9@3442.42,2700.87
  Bottom Layer w10: J6.3@2942.75,3574.8 2943.77,3574.8 3160.48,3358.1 TP10.1@3161.49,3358.1 3170.67,3348.91 3170.67,2837.19 v1@3286.91,2720.95 ; v1(3287.67,2721.05) v1@3290.28,2718.44
NetJ5_11: J5.11 J6.2 TP11.1 | length 1244.7
  Top Layer w10: v1(3171.08,2788.72) 3285.59,2674.22 3437.58,2674.22 J5.11@3442.42,2669.38
  Bottom Layer w10: J6.2@2842.75,3574.8 2842.75,3473.8 TP11.1@2958.46,3358.1 2958.46,3242.42 3113.44,3087.45 3113.44,2843.97 v1@3170.67,2786.74
NetJ5_55: J5.55 R85.2 | length 108
  Top Layer w10: R85.2@3334.47,1976.46 J5.55@3442.42,1976.46
NetJ5_57: J5.57 R87.2 | length 108
  Top Layer w10: R87.2@3334.47,1818.98 J5.57@3442.42,1818.98
NetJ5_58: J5.58 R88.1 | length 3193.5
  Top Layer w10: R88.1@2001.97,3374.02 2010.96,3374.02 2014.47,3370.51 2014.47,3361.52 2023.35,3352.64 2277.25,3352.64 2425.97,3203.91 3426.01,3203.91 3781.02,2848.9 3781.02,1893.61 3705.51,1818.09 3577.17,1818.09 J5.58@3576.28,1818.98
NetJ5_60: J5.60 R89.1 | length 3082.9
  Top Layer w10: R89.1@2163.66,3373.03 2282.13,3373.03 2433.38,3221.78 3433.42,3221.78 3798.9,2856.3 3798.9,1886.2 3700.18,1787.49 J5.60@3576.28,1787.49
NetJ5_61: J5.61 R92.2 | length 111.8
  Top Layer w10: R92.2@3330.63,1755.99 J5.61@3442.42,1755.99
NetJ5_62: J5.62 R93.1 | length 2984.1
  Top Layer w10: R93.1@2325.35,3375.51 2332.85,3375.51 2337.85,3370.51 2337.85,3363.01 2461.21,3239.66 3440.82,3239.66 3816.77,2863.7 3816.77,1878.8 3693.97,1755.99 J5.62@3576.28,1755.99
NetJ5_64: J5.64 R94.1 | length 2875.5
  Top Layer w10: R94.1@2487.05,3375.51 2605.03,3257.53 3448.22,3257.53 3834.65,2871.11 3834.65,1871.39 3687.75,1724.5 J5.64@3576.28,1724.5
NetJ5_69: J5.69 R95.2 | length 123.1
  Top Layer w10: R95.2@3327.87,1644.2 3327.87,1639.7 3337.56,1630.01 J5.69@3442.42,1630.01
NetJ5_73: J5.73 R96.2 | length 108.2
  Top Layer w10: R96.2@3334.47,1566.43 3334.77,1566.72 3442.13,1566.72 J5.73@3442.42,1567.02
NetJ5_81: J5.81 R97.2 | length 108
  Top Layer w10: R97.2@3334.47,1441.03 J5.81@3442.42,1441.03
NetR1_2: R1.2 R2.1 U1.4 | length 157.9
  Bottom Layer w10: R1.2@1457.97,3133.87 1457.97,3126.37 1445.28,3113.68 R2.1@1445.28,3083.94 1522.35,3083.94 1522.51,3083.78 1530.39,3083.78 1537.2,3076.97 U1.4@1537.2,3069.09
NetR6_2: R6.2 R7.1 U2.4 | length 144.3
  Bottom Layer w10: R6.2@1450.05,2441.97 1450.05,2392.79 R7.1@1450.81,2392.04 1458.31,2392.04 1476.76,2373.58 U2.4@1537.2,2373.58
NetR11_2: R11.2 R12.1 U3.4 | length 167.5
  Bottom Layer w10: R11.2@1453.97,1747.78 1453.97,1740.28 1440.7,1727.01 R12.1@1440.7,1685.41 1448.2,1685.41 1455.54,1678.07 U3.4@1537.2,1678.07 U3.4@1537.2,1678.03
NetR16_2: R16.2 R17.1 U4.4 | length 138.3
  Bottom Layer w10: R16.2@1446.6,1040.4 R17.1@1446.6,999.99 1454.1,999.99 1467.23,986.86 1532.84,986.86 U4.4@1537.2,982.5
NetR46_1: R46.1 U7.23 | length 94.8
  Bottom Layer w10: U7.23@3013.66,1580.5 3013.74,1580.43 3027.84,1580.43 3062.5,1545.77 R46.1@3062.5,1514.21
NetR47_1: R47.1 U7.25 | length 138.6
  Bottom Layer w10: U7.25@2988.07,1535.23 2988.07,1528.5 3018.93,1497.64 3018.93,1474.84 3062.01,1431.75 R47.1@3062.01,1427.25
NetR48_1: R48.1 U7.24 | length 110.6
  Bottom Layer w10: U7.24@3013.66,1560.82 3013.66,1546.67 3036.81,1523.53 3036.81,1500.61 3062.45,1474.97 R48.1@3062.45,1470.47
NetR75_1: R75.1 U5.8 U5.9 | length 362.9
  Top Layer w10: v1(2098.03,3122) 2142.35,3122 2167.7,3096.65 2218.66,3096.65 v1(2241.31,3119.31)
  Bottom Layer w10: U5.8@2024.45,3085.83 2078.89,3085.83 2095.42,3102.36 2095.42,3119.39 v1(2098.03,3122) 2095.47,3124.56 2095.47,3148.81 2090.47,3153.81 R75.1@2090.47,3181.78 ; v1(2241.31,3119.31) 2241.31,3118.64 2252.8,3107.16 U5.9@2252.8,3085.83
NetR76_2: R76.2 U6.8 U6.9 | length 359.3
  Top Layer w10: v1(2091.17,2431.84) 2121.88,2401.14 2218.66,2401.14 v1(2241.31,2423.8)
  Bottom Layer w10: U6.8@2024.45,2390.31 2074.32,2390.31 2085.15,2401.14 2085.15,2425.82 v1(2091.17,2431.84) R76.2@2091.17,2482.24 ; v1(2241.31,2423.8) 2241.31,2423.13 2252.79,2411.64 U6.9@2252.8,2390.31
NetR77_1: R77.1 U8.8 U8.9 | length 351.6
  Top Layer w10: v1(2092.83,1737) 2124.2,1705.63 2218.66,1705.63 v1@2241.31,1728.28
  Bottom Layer w10: U8.8@2024.45,1694.8 2070.7,1694.8 2092.83,1716.93 v1(2092.83,1737) 2091.64,1738.19 2091.64,1774.72 R77.1@2090.44,1775.92 ; v1(2240.83,1728.28) 2240.83,1698.66 2244.69,1694.8 U8.9@2252.8,1694.8
NetR78_1: R78.1 U9.8 U9.9 | length 344.5
  Top Layer w10: v1(2088.74,1037.54) 2116.16,1010.12 2218.66,1010.12 v1@2241.31,1032.77
  Bottom Layer w10: U9.8@2024.45,999.29 2070.7,999.29 2088.74,1017.33 v1(2088.74,1037.54) R78.1@2088.74,1073.6 ; v1(2240.83,1032.77) 2240.83,1003.15 2244.69,999.29 U9.9@2252.8,999.29
NetR79_1: R79.1 R81.2 U11.12 | length 158.5
  Bottom Layer w10: U11.12@3148.79,2544.38 3152.65,2548.24 3182.51,2548.24 3216.96,2582.69 3216.96,2603.31 3221.96,2608.31 R81.2@3229.46,2608.31 3230.23,2609.08 R79.1@3230.23,2647.25
NetR80_1: R80.1 R82.2 U11.5 | length 146.9
  Bottom Layer w10: R82.2@2847.01,2642.51 2848.47,2642.51 2853.47,2637.51 R80.1@2853.47,2595.56 2858.47,2590.56 2858.47,2576.48 2872.62,2562.34 2886.72,2548.24 2916.58,2548.24 U11.5@2920.44,2544.38
NetR83_1: R83.1 R90.2 U11.3 | length 141.2
  Bottom Layer w10: R90.2@2838.46,2416.11 2838.66,2416.32 2838.66,2468.28 R83.1@2838.87,2468.49 ; R83.1@2838.87,2475.99 2843.87,2480.99 2851.37,2480.99 2859.72,2489.34 2916.58,2489.34 U11.3@2920.44,2493.2
NetR84_1: R84.1 R91.2 U11.14 | length 135.3
  Bottom Layer w10: U11.14@3148.79,2493.2 3152.65,2489.34 3187.85,2489.34 3221.96,2455.22 R91.2@3229.46,2455.22 3230.23,2454.46 R84.1@3230.23,2416.68
NetR98_1: R98.1 U11.8 U11.9 | length 288
  Bottom Layer w10: U11.8@2920.44,2621.15 3011.73,2621.15 ; R98.1@3010.82,2680.38 3011.73,2679.47 3011.73,2621.15 ; U11.9@3148.79,2621.15 3011.73,2621.15
NetR104_1: R104.1 R105.2 U12.1 | length 0.2
  Bottom Layer w10: U12.1@2475.77,364.83 U12.1@2475.89,364.71
NetR105_1: R105.1 R112.2 U12.2 | length 102.8
  Bottom Layer w7.87: U12.2@2494.59,358.81 2494.59,390.69 R105.1@2505.89,401.99
  Bottom Layer w10: R105.1@2505.77,408.41 R105.1@2505.77,415.91 ; R105.1@2505.89,409.49 R112.2@2505.89,456.89
NetR107_1: R107.1 R114.2 U13.6 | length 197.1
  Bottom Layer w10: U13.6@2998.04,452.51 3072.42,452.51 3102.96,421.97 R114.2@3110.46,421.97 3117.96,421.97 3149.87,453.88 R107.1@3149.87,454.47 ; R107.1@3147.91,452.51 R107.1@3149.87,454.47 ; R107.1@3163.43,460.53 3155.93,460.53 R107.1@3149.87,454.47
NetR109_1: R109.1 U14.5 | length 39.8
  Bottom Layer w10: U14.5@2835.41,908.01 2874.87,908.01 R109.1@2875.1,907.78
NetR110_1: R110.1 R115.2 U14.2 | length 129.2
  Bottom Layer w10: R115.2@2707.17,989.84 2707.17,937.78 2706.94,937.54 2706.94,915.49 2714.41,908.01 U14.2@2758.64,908.01
NetR113_2: R113.2 U12.9 | length 51.5
  Bottom Layer w7.87: R113.2@2480.94,246.45 2488.44,246.45 2494.51,252.51 2494.51,260.01 2494.59,260.1 U12.9@2494.59,287.94
NetR118_1: R118.1 R119.2 U15.4 | length 154.7
  Bottom Layer w10: R119.2@2988.2,1011.88 3024.26,1011.88 3041.44,1029.06 3075.22,1029.06 R118.1@3076.14,1028.15 3074.73,1026.74 3074.73,971.45 U15.4@3073.33,970.05
Vin: C72.1 J7.2 R104.2 U12.5
pads on no net: FID1.1 FID2.1 FID3.1 FID4.1 FID5.1 FID6.1 H1.1 H2.1 H3.1 H4.1 H5.0 H6.0 H7.0 H8.0 J5.1 J5.2 J5.3 J5.4 J5.5 J5.6 J5.8 J5.12 J5.14 J5.15 J5.17 J5.21 J5.23 J5.24 J5.26 J5.28 J5.30 J5.31 J5.32 J5.33 J5.34 J5.36 J5.37 J5.39 J5.40 J5.41 J5.42 J5.43 J5.44 J5.45 J5.50 J5.52 J5.53 J5.54 J5.56 J5.59 J5.63 J5.66 J5.72 J5.74 J5.76 J5.77 J5.78 J5.80 J5.82 J5.87 J5.88 J5.89 J5.90 J5.91 J5.92 J5.93 J5.94 J5.95 J5.96 J5.99 J5.100 J5.101 J5.102 J5.103 J5.104 J5.105 J5.106 J5.107 J5.108 J5.109 J5.110 J5.113 J5.114 J5.115 J5.116 J5.117 J5.118 J5.119 J5.120 J5.181 J5.182 J5.185 J5.186 LBL1.0 U7. U10.1 U10.3 U10.7 U10.8 U12.3 U12.4 U14.7@2797.02,890.3 U14.7@2797.02,925.73

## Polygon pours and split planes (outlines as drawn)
GND on Top Layer "TOP_LAYER_GND_P405" (solid, remove dead copper, pour order 405): 2889.32,728.37 2889.32,95.77 3205.22,95.77 3205.22,728.37
CH4- on Top Layer "TOP_LAYER_CH4-_P380" (solid, remove dead copper, pour order 380): 286.35,769.55 693.23,769.55 693.23,596.49 286.35,596.49
CH3- on Top Layer "TOP_LAYER_CH3-_P376" (solid, remove dead copper, pour order 376): 286.35,1465.09 693.23,1465.09 693.23,1292.02 286.35,1292.02
CH1- on Top Layer "TOP_LAYER_CH1-_P372" (solid, remove dead copper, pour order 372): 286.35,2856.16 693.23,2856.16 693.23,2683.1 286.35,2683.1
CH2- on Top Layer "TOP_LAYER_CH2-_P368" (solid, remove dead copper, pour order 368): 287.97,2160.62 694.86,2160.62 694.86,1987.56 287.97,1987.56
CH4+ on Top Layer "TOP_LAYER_CH4+_P365" (solid, remove dead copper, pour order 365): 287.4,944.88 694.29,944.88 694.29,1091.55 287.4,1091.55
CH3+ on Top Layer "TOP_LAYER_CH3+_P361" (solid, remove dead copper, pour order 361): 287.4,1640.42 694.29,1640.42 694.29,1787.09 287.4,1787.09
CH2+ on Top Layer "TOP_LAYER_CH2+_P357" (solid, remove dead copper, pour order 357): 289.03,2335.96 695.91,2335.96 695.91,2482.63 289.03,2482.63
CH1+ on Top Layer "TOP_LAYER_CH1+_P353" (solid, remove dead copper, pour order 353): 287.4,3031.5 694.29,3031.5 694.29,3178.17 287.4,3178.17
CT4_OUT- on Bottom Layer "BOTTOM_LAYER_CT4_OUT-_P436" (solid, remove dead copper, pour order 436): 1176.65,563.83 1176.65,826.13 1307.05,826.13 1352.98,780.2 1370.9,780.2 1422.07,729.02 1495.52,729.02 1495.52,623.4 1421.19,623.4 1327.09,623.4 1327.09,562.94
CT3_OUT- on Bottom Layer "BOTTOM_LAYER_CT3_OUT-_P435" (solid, remove dead copper, pour order 435): 1176.65,1259.36 1176.65,1517.64 1311.07,1517.64 1352.98,1475.73 1370.9,1475.73 1422.07,1424.56 1495.51,1424.56 1495.51,1318.93 1421.19,1318.93 1327.09,1318.93 1327.09,1258.47
CT2_OUT- on Bottom Layer "BOTTOM_LAYER_CT2_OUT-_P434" (solid, remove dead copper, pour order 434): 1176.65,1954.89 1176.65,2213.17 1311.07,2213.17 1352.98,2171.26 1370.9,2171.26 1422.07,2120.09 1495.51,2120.09 1495.51,2014.46 1421.19,2014.46 1327.09,2014.46 1327.09,1954
GND on Bottom Layer "Bottom Layer-GND" (solid, pour order 433): 2864.62,1432.58 2894.62,1432.58 2894.62,1561.37 2922.78,1561.37 2922.78,1514.06 2936.1,1500.74 2936.1,1429.43 2955.95,1429.38 2955.95,1499.6 2934.6,1520.95 2934.6,1561.37 2986.57,1561.37 2988.07,1562.88 2988.07,1698.49 2972.61,1698.49 2973.32,1699.2 2973.32,1737.42 2944.02,1737.42 2944.02,1698.49 2851.77,1698.49 2851.7,1664.72 2810.8,1664.97 2786.71,1689.06 2757.87,1689.06 2757.87,1642.18 2797.34,1642.18 2809.72,1654.56 2851.68,1654.56 2851.54,1587.52 2814.96,1587.52 2775.6,1548.15 2760.06,1548.15 2760.06,1525.61 2806.29,1525.61 2851.51,1570.83 2851.49,1561.37 2883.41,1561.37 2883.41,1525.61 2864.62,1506.83
2V5 on Bottom Layer "BOTTOM_LAYER_2V5_P430" (solid, remove dead copper, pour order 430): 2870.9,2095.25 2870.97,2095.32 2883.49,2095.32 2883.49,1999.36 2927.95,1954.9 2927.95,1888.16 2792.44,1888.16 2789.88,1890.73 2790.75,1891.6 2790.75,1966.88 2831.83,1966.88 2850.84,1985.89 2850.84,2032.01 2862.19,2043.36 2862.19,2095.25
NetC85_1 on Bottom Layer "BOTTOM_LAYER_NETC85_1_P412" (solid, pour order 412): 3191.88,749.77 3191.88,815.81 3167.37,840.32 3135.97,840.32 3135.97,879.58 3179.21,879.58 3195.94,862.85 3196.07,862.97 3252.16,862.97 3252.16,749.48
5V on Bottom Layer "BOTTOM_LAYER_5V_P406" (solid, remove dead copper, pour order 406): 2767.54,888.43 2767.54,872.57 2730.77,835.79 2730.77,795.95 2571.76,795.95 2571.76,890.57 2767.14,890.57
